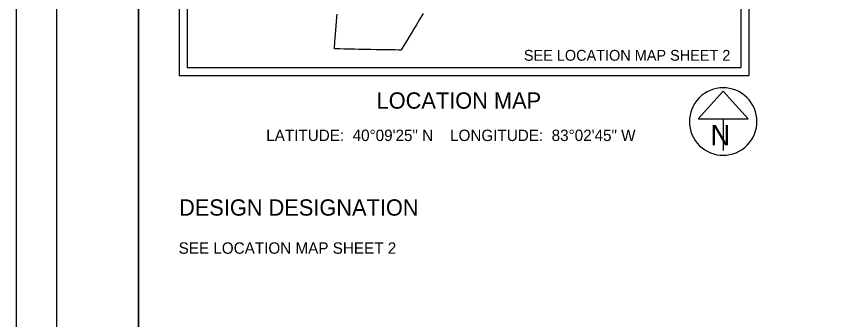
# Model space of a CAD drawing. Extents: x 0 to 34, y 0 to 22.
# Drawn here: x 0 to 9.99, y 11 to 14.73 of the extents above; entities that cross this region are included whole.
import ezdxf

# ---------------------------------------------------------------- set-up
doc = ezdxf.new("R2010")
doc.units = 0
for name, color, linetype in [('GM_X_County', 7, 'Continuous'), ('SH_Border', 7, 'Continuous'), ('SH_Cut_Line', 7, 'Continuous'), ('SH_Data', 7, 'Continuous'), ('SH_Text', 7, 'Continuous')]:
    doc.layers.add(name, color=color, linetype=linetype)

msp = doc.modelspace()

# ---------------------------------------------------------------- linework, layer by layer
at = {"layer": 'GM_X_County'}
for p, q in [((3.9258, 14.5598), (3.9382, 14.7199)), ((3.9382, 14.7199), (3.9409, 14.7543)), ((4.9988, 14.7636), (4.954, 14.6895)), ((4.9157, 14.6252), (4.8773, 14.5616)), ((4.954, 14.6895), (4.9157, 14.6252)), ((3.9153, 14.4243), (3.9214, 14.5027)), ((3.9214, 14.5027), (3.9217, 14.507)), ((3.9217, 14.507), (3.9258, 14.5598)), ((4.8704, 14.5501), (4.8304, 14.4836)), ((4.8769, 14.5609), (4.8704, 14.5501)), ((4.877, 14.561), (4.8769, 14.5609)), ((4.8773, 14.5616), (4.877, 14.561)), ((3.908, 14.3293), (3.9152, 14.4225)), ((3.9152, 14.4225), (3.9153, 14.4243)), ((4.8021, 14.4367), (4.7732, 14.3885)), ((4.8304, 14.4836), (4.8021, 14.4367)), ((3.9176, 14.3291), (3.908, 14.3293)), ((3.9723, 14.3278), (3.9176, 14.3291)), ((4.0264, 14.3264), (3.9723, 14.3278)), ((4.0813, 14.3251), (4.0264, 14.3264)), ((4.1576, 14.3232), (4.0813, 14.3251)), ((4.2041, 14.3221), (4.1576, 14.3232)), ((4.2443, 14.3211), (4.2041, 14.3221)), ((4.2497, 14.3209), (4.2443, 14.3211)), ((4.2723, 14.3206), (4.2497, 14.3209)), ((4.3539, 14.3194), (4.2723, 14.3206)), ((4.4199, 14.3184), (4.3539, 14.3194)), ((4.4969, 14.3173), (4.4199, 14.3184)), ((4.4986, 14.3173), (4.4969, 14.3173)), ((4.5316, 14.3168), (4.4986, 14.3173)), ((4.5893, 14.316), (4.5316, 14.3168)), ((4.6298, 14.3154), (4.5893, 14.316)), ((4.6547, 14.315), (4.6298, 14.3154)), ((4.6942, 14.3144), (4.6547, 14.315)), ((4.7193, 14.3141), (4.6942, 14.3144)), ((4.7283, 14.3139), (4.7193, 14.3141)), ((4.7295, 14.3159), (4.7283, 14.3139)), ((4.7732, 14.3885), (4.7295, 14.3159))]:
    msp.add_line(p, q, dxfattribs=at)
at = {"layer": 'SH_Border'}
for points in [[(0.5, 21.5), (1.5, 21.5), (1.5, 0.5), (0.5, 0.5)], [(1.5, 21.5), (33.5, 21.5), (33.5, 0.5), (1.5, 0.5)]]:
    msp.add_lwpolyline(points, close=True, dxfattribs=at)
at = {"layer": 'SH_Cut_Line'}
msp.add_lwpolyline([(0, 0), (34, 0), (34, 22), (0, 22)], close=True, dxfattribs=at)
at = {"layer": 'SH_Data'}
for p, q in [((2, 21), (2, 14)), ((9, 21), (9, 14)), ((2.1, 20.9), (2.1, 14.1)), ((8.9, 20.9), (8.9, 14.1)), ((2.1, 14.1), (8.9, 14.1)), ((2.1, 14.1), (2.1, 14.1)), ((2, 14), (9, 14)), ((8.6845, 13.8091), (8.3769, 13.4678)), ((8.9921, 13.4678), (8.6845, 13.8091)), ((8.3769, 13.4678), (8.9921, 13.4678)), ((8.6845, 13.4678), (8.6845, 13.0811)), ((8.6845, 13.4353), (8.6845, 13.4353)), ((8.6845, 13.4353), (8.6845, 13.4353))]:
    msp.add_line(p, q, dxfattribs=at)
msp.add_arc((8.6845, 13.4353), 0.4148, 129.77984, 129.76332, dxfattribs=at)

# ---------------------------------------------------------------- texts
for s, height, p in [('SEE LOCATION MAP SHEET 2', 0.132821, (6.2362, 14.1828)), ('N', 0.25, (8.5292, 13.144)), ('DESIGN DESIGNATION', 0.2, (2, 12.2792))]:
    msp.add_text(s, height=height, dxfattribs=at).set_placement(p)
at = {"layer": 'SH_Text'}
for s, height, p in [('LOCATION MAP', 0.2, (4.4269, 13.5938)), ('LATITUDE:  40°09\'25" N    LONGITUDE:  83°02\'45" W', 0.14, (3.071, 13.1959)), ('SEE LOCATION MAP SHEET 2', 0.14, (1.9944, 11.8108))]:
    msp.add_text(s, height=height, dxfattribs=at).set_placement(p)

doc.saveas('drawing.dxf')
